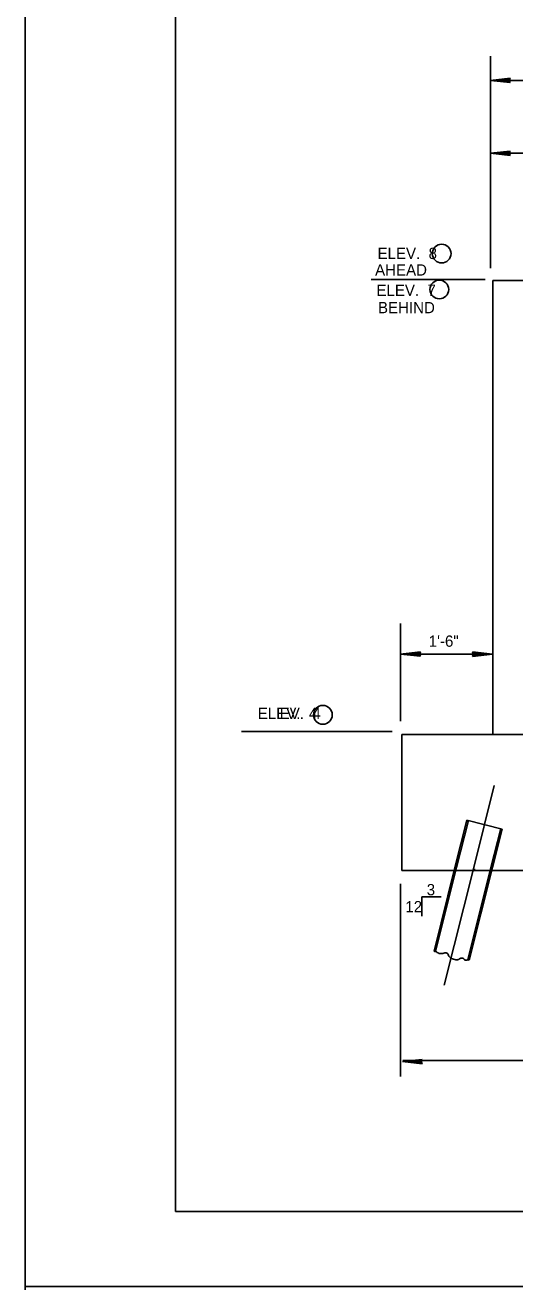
# Model space of a CAD drawing. Extents: x 1.6 to 6.29, y 2.8 to 7.08.
# Drawn here: x 2.391 to 2.935, y 4.671 to 6.075 of the extents above; entities that cross this region are included whole.
import ezdxf

# ---------------------------------------------------------------- set-up
doc = ezdxf.new("R2010")
doc.units = 0
doc.layers.add('Level 1', color=7, linetype='Continuous')
doc.layers.add('Level 5', color=7, linetype='Continuous')

msp = doc.modelspace()

# ---------------------------------------------------------------- linework, layer by layer
at = {"layer": 'Level 1'}
for p, q in [((2.3914, 7.0849), (2.3914, 4.6712)), ((2.5581, 6.998), (2.5581, 4.758)), ((2.9077, 5.8055), (2.9077, 6.041)), ((2.9077, 6.0142), (2.9297, 6.0167)), ((2.9077, 6.0142), (3.2259, 6.0142)), ((2.9297, 6.0142), (2.9077, 6.0142)), ((2.9297, 6.0118), (2.9077, 6.0142)), ((2.9133, 6.0146), (2.9107, 6.0143)), ((2.9107, 6.0143), (2.9282, 6.0144)), ((2.9113, 6.014), (2.9133, 6.0146)), ((2.9212, 6.0136), (2.9113, 6.014)), ((2.9292, 6.0121), (2.9128, 6.0139)), ((2.9292, 6.0122), (2.9128, 6.0139)), ((2.9292, 6.012), (2.9128, 6.0138)), ((2.9293, 6.0125), (2.9129, 6.0142)), ((2.9292, 6.0122), (2.9129, 6.0141)), ((2.9292, 6.0162), (2.9139, 6.0146)), ((2.9292, 6.0161), (2.9139, 6.0144)), ((2.9293, 6.0158), (2.914, 6.0142)), ((2.9293, 6.0156), (2.914, 6.0139)), ((2.9173, 6.0139), (2.9286, 6.0152)), ((2.9285, 6.0147), (2.9173, 6.0139)), ((2.9184, 6.0137), (2.9184, 6.014)), ((2.9184, 6.014), (2.9203, 6.0139)), ((2.9282, 6.0139), (2.9184, 6.0137)), ((2.9203, 6.0139), (2.9282, 6.0137)), ((2.9287, 6.013), (2.9212, 6.0136)), ((2.9282, 6.0137), (2.9219, 6.0136)), ((2.9219, 6.0136), (2.9285, 6.0134)), ((2.9282, 6.0144), (2.9231, 6.0147)), ((2.9231, 6.0147), (2.9285, 6.0147)), ((2.9285, 6.0134), (2.9238, 6.0133)), ((2.9238, 6.0133), (2.9287, 6.013)), ((2.9282, 6.0136), (2.9276, 6.0133)), ((2.9276, 6.0133), (2.928, 6.0127)), ((2.928, 6.0127), (2.9283, 6.0142)), ((2.9286, 6.0152), (2.9282, 6.0139)), ((2.9282, 6.0139), (2.9291, 6.0124)), ((2.9286, 6.0127), (2.9282, 6.0136)), ((2.9283, 6.0142), (2.9287, 6.0152)), ((2.9297, 6.0167), (2.9286, 6.0142)), ((2.9286, 6.0142), (2.9297, 6.0118)), ((2.9291, 6.0124), (2.9286, 6.0127)), ((2.9287, 6.0152), (2.9292, 6.0162)), ((2.9077, 5.9333), (3.5143, 5.9333)), ((2.9078, 5.9333), (2.9298, 5.9357)), ((2.9298, 5.9333), (2.9078, 5.9333)), ((2.9298, 5.9308), (2.9078, 5.9333)), ((2.9134, 5.9337), (2.9107, 5.9334)), ((2.9107, 5.9334), (2.9283, 5.9335)), ((2.9114, 5.9331), (2.9134, 5.9337)), ((2.9213, 5.9327), (2.9114, 5.9331)), ((2.9293, 5.9312), (2.9129, 5.933)), ((2.9293, 5.9312), (2.9129, 5.933)), ((2.9293, 5.9311), (2.9129, 5.9329)), ((2.9294, 5.9316), (2.913, 5.9333)), ((2.9293, 5.9313), (2.913, 5.9332)), ((2.9293, 5.9353), (2.914, 5.9337)), ((2.9293, 5.9352), (2.914, 5.9335)), ((2.9294, 5.9349), (2.9141, 5.9333)), ((2.9294, 5.9347), (2.9141, 5.933)), ((2.9173, 5.933), (2.9287, 5.9342)), ((2.9286, 5.9338), (2.9173, 5.933)), ((2.9185, 5.9328), (2.9185, 5.9331)), ((2.9185, 5.9331), (2.9204, 5.933)), ((2.9283, 5.933), (2.9185, 5.9328)), ((2.9204, 5.933), (2.9283, 5.9328)), ((2.9287, 5.9321), (2.9213, 5.9327)), ((2.9283, 5.9328), (2.922, 5.9327)), ((2.922, 5.9327), (2.9286, 5.9325)), ((2.9283, 5.9335), (2.9232, 5.9338)), ((2.9232, 5.9338), (2.9286, 5.9338)), ((2.9286, 5.9325), (2.9239, 5.9323)), ((2.9239, 5.9323), (2.9287, 5.9321)), ((2.9282, 5.9327), (2.9277, 5.9324)), ((2.9277, 5.9324), (2.9281, 5.9318)), ((2.9281, 5.9318), (2.9284, 5.9333)), ((2.9287, 5.9342), (2.9282, 5.933)), ((2.9282, 5.933), (2.9292, 5.9315)), ((2.9287, 5.9318), (2.9282, 5.9327)), ((2.9284, 5.9333), (2.9288, 5.9342)), ((2.9298, 5.9357), (2.9287, 5.9333)), ((2.9287, 5.9333), (2.9298, 5.9308)), ((2.9292, 5.9315), (2.9287, 5.9318)), ((2.9288, 5.9342), (2.9293, 5.9353)), ((2.7752, 5.793), (2.9018, 5.793)), ((2.9103, 5.2879), (2.9103, 5.7921)), ((2.9103, 5.7921), (3.2292, 5.7921)), ((2.9103, 5.2879), (2.9103, 5.4659)), ((2.8079, 5.3027), (2.8079, 5.4109)), ((2.8079, 5.3027), (2.8079, 5.3861)), ((2.8079, 5.377), (2.83, 5.3795)), ((2.8079, 5.377), (2.83, 5.3795)), ((2.8295, 5.3791), (2.8142, 5.3774)), ((2.8295, 5.3791), (2.8142, 5.3774)), ((2.8295, 5.3789), (2.8142, 5.3773)), ((2.8295, 5.3789), (2.8142, 5.3773)), ((2.8296, 5.3787), (2.8142, 5.377)), ((2.8296, 5.3787), (2.8142, 5.377)), ((2.8296, 5.3784), (2.8142, 5.3767)), ((2.8296, 5.3784), (2.8142, 5.3767)), ((2.83, 5.3795), (2.8288, 5.377)), ((2.83, 5.3795), (2.8288, 5.377)), ((2.829, 5.378), (2.8295, 5.3791)), ((2.829, 5.378), (2.8295, 5.3791)), ((2.8878, 5.3794), (2.9101, 5.377)), ((2.889, 5.377), (2.8878, 5.3794)), ((2.8878, 5.3794), (2.9101, 5.377)), ((2.889, 5.377), (2.8878, 5.3794)), ((2.8882, 5.3791), (2.9048, 5.3773)), ((2.8882, 5.3791), (2.9048, 5.3773)), ((2.8882, 5.379), (2.9048, 5.3772)), ((2.8882, 5.379), (2.9048, 5.3772)), ((2.8882, 5.3789), (2.9048, 5.3771)), ((2.8882, 5.3789), (2.9048, 5.3771)), ((2.8882, 5.3787), (2.9048, 5.3768)), ((2.8882, 5.3787), (2.9048, 5.3768)), ((2.8883, 5.3792), (2.9048, 5.3773)), ((2.8883, 5.3792), (2.9048, 5.3773)), ((2.8894, 5.3772), (2.8884, 5.3788)), ((2.8884, 5.3788), (2.8889, 5.3784)), ((2.8894, 5.3772), (2.8884, 5.3788)), ((2.8884, 5.3788), (2.8889, 5.3784)), ((2.8937, 5.3779), (2.8888, 5.3782)), ((2.8888, 5.3782), (2.8965, 5.3776)), ((2.8937, 5.3779), (2.8888, 5.3782)), ((2.8888, 5.3782), (2.8965, 5.3776)), ((2.8889, 5.3784), (2.8894, 5.3776)), ((2.8889, 5.3784), (2.8894, 5.3776)), ((2.8895, 5.3785), (2.8892, 5.3769)), ((2.8895, 5.3785), (2.8892, 5.3769)), ((2.8899, 5.3778), (2.8895, 5.3785)), ((2.8899, 5.3778), (2.8895, 5.3785)), ((2.83, 5.377), (2.8079, 5.377)), ((2.83, 5.3746), (2.8079, 5.377)), ((2.83, 5.377), (2.8079, 5.377)), ((2.83, 5.3746), (2.8079, 5.377)), ((2.8081, 5.377), (2.9072, 5.377)), ((2.8081, 5.377), (2.9072, 5.377)), ((2.8136, 5.3774), (2.8109, 5.3772)), ((2.8136, 5.3774), (2.8109, 5.3772)), ((2.8109, 5.3772), (2.8285, 5.3773)), ((2.8109, 5.3772), (2.8285, 5.3773)), ((2.8116, 5.3768), (2.8136, 5.3774)), ((2.8116, 5.3768), (2.8136, 5.3774)), ((2.8214, 5.3764), (2.8116, 5.3768)), ((2.8214, 5.3764), (2.8116, 5.3768)), ((2.8295, 5.3748), (2.8131, 5.3767)), ((2.8295, 5.3749), (2.8131, 5.3767)), ((2.8295, 5.375), (2.8131, 5.3767)), ((2.8295, 5.3748), (2.8131, 5.3767)), ((2.8295, 5.3749), (2.8131, 5.3767)), ((2.8295, 5.375), (2.8131, 5.3767)), ((2.8296, 5.3753), (2.8132, 5.3771)), ((2.8296, 5.3753), (2.8132, 5.3771)), ((2.8295, 5.3751), (2.8132, 5.3769)), ((2.8295, 5.3751), (2.8132, 5.3769)), ((2.8175, 5.3767), (2.8288, 5.378)), ((2.8175, 5.3767), (2.8288, 5.378)), ((2.8287, 5.3776), (2.8175, 5.3767)), ((2.8287, 5.3776), (2.8175, 5.3767)), ((2.8187, 5.3766), (2.8187, 5.3768)), ((2.8187, 5.3768), (2.8206, 5.3767)), ((2.8187, 5.3766), (2.8187, 5.3768)), ((2.8187, 5.3768), (2.8206, 5.3767)), ((2.8285, 5.3767), (2.8187, 5.3766)), ((2.8285, 5.3767), (2.8187, 5.3766)), ((2.8206, 5.3767), (2.8285, 5.3766)), ((2.8206, 5.3767), (2.8285, 5.3766)), ((2.8289, 5.3758), (2.8214, 5.3764)), ((2.8289, 5.3758), (2.8214, 5.3764)), ((2.8285, 5.3766), (2.8222, 5.3764)), ((2.8285, 5.3766), (2.8222, 5.3764)), ((2.8222, 5.3764), (2.8287, 5.3762)), ((2.8222, 5.3764), (2.8287, 5.3762)), ((2.8285, 5.3773), (2.8233, 5.3776)), ((2.8233, 5.3776), (2.8287, 5.3776)), ((2.8285, 5.3773), (2.8233, 5.3776)), ((2.8233, 5.3776), (2.8287, 5.3776)), ((2.8287, 5.3762), (2.8241, 5.3761)), ((2.8287, 5.3762), (2.8241, 5.3761)), ((2.8241, 5.3761), (2.8289, 5.3758)), ((2.8241, 5.3761), (2.8289, 5.3758)), ((2.8284, 5.3764), (2.8278, 5.3762)), ((2.8284, 5.3764), (2.8278, 5.3762)), ((2.8278, 5.3762), (2.8282, 5.3755)), ((2.8278, 5.3762), (2.8282, 5.3755)), ((2.8282, 5.3755), (2.8286, 5.3771)), ((2.8282, 5.3755), (2.8286, 5.3771)), ((2.8288, 5.378), (2.8284, 5.3767)), ((2.8288, 5.378), (2.8284, 5.3767)), ((2.8284, 5.3767), (2.8293, 5.3752)), ((2.8284, 5.3767), (2.8293, 5.3752)), ((2.8288, 5.3756), (2.8284, 5.3764)), ((2.8288, 5.3756), (2.8284, 5.3764)), ((2.8286, 5.3771), (2.829, 5.378)), ((2.8286, 5.3771), (2.829, 5.378)), ((2.8288, 5.377), (2.83, 5.3746)), ((2.8288, 5.377), (2.83, 5.3746)), ((2.8293, 5.3752), (2.8288, 5.3756)), ((2.8293, 5.3752), (2.8288, 5.3756)), ((2.8878, 5.377), (2.9101, 5.377)), ((2.9101, 5.377), (2.8878, 5.3745)), ((2.8878, 5.3745), (2.889, 5.377)), ((2.8878, 5.377), (2.9101, 5.377)), ((2.9101, 5.377), (2.8878, 5.3745)), ((2.8878, 5.3745), (2.889, 5.377)), ((2.8882, 5.3756), (2.9037, 5.3773)), ((2.8882, 5.3756), (2.9037, 5.3773)), ((2.8882, 5.3753), (2.9037, 5.377)), ((2.8882, 5.3753), (2.9037, 5.377)), ((2.8882, 5.3751), (2.9038, 5.3767)), ((2.8882, 5.3751), (2.9038, 5.3767)), ((2.8883, 5.3748), (2.9038, 5.3766)), ((2.8883, 5.3748), (2.9038, 5.3766)), ((2.8887, 5.376), (2.8883, 5.3749)), ((2.8887, 5.376), (2.8883, 5.3749)), ((2.8892, 5.3769), (2.8887, 5.376)), ((2.8892, 5.3769), (2.8887, 5.376)), ((2.9003, 5.3772), (2.8889, 5.376)), ((2.8889, 5.376), (2.8894, 5.3772)), ((2.9003, 5.3772), (2.8889, 5.376)), ((2.8889, 5.376), (2.8894, 5.3772)), ((2.8891, 5.3777), (2.8937, 5.3779)), ((2.8891, 5.3777), (2.8937, 5.3779)), ((2.8958, 5.3776), (2.8891, 5.3777)), ((2.8958, 5.3776), (2.8891, 5.3777)), ((2.8891, 5.3764), (2.9003, 5.3772)), ((2.8891, 5.3764), (2.9003, 5.3772)), ((2.8945, 5.3764), (2.8891, 5.3764)), ((2.8945, 5.3764), (2.8891, 5.3764)), ((2.8893, 5.3774), (2.8958, 5.3776)), ((2.8893, 5.3774), (2.8958, 5.3776)), ((2.8893, 5.3773), (2.8992, 5.3774)), ((2.8973, 5.3773), (2.8893, 5.3774)), ((2.8893, 5.3773), (2.8992, 5.3774)), ((2.8973, 5.3773), (2.8893, 5.3774)), ((2.9071, 5.3768), (2.8893, 5.3767)), ((2.9071, 5.3768), (2.8893, 5.3767)), ((2.8893, 5.3767), (2.8945, 5.3764)), ((2.8893, 5.3767), (2.8945, 5.3764)), ((2.8894, 5.3776), (2.8899, 5.3778)), ((2.8894, 5.3776), (2.8899, 5.3778)), ((2.8965, 5.3776), (2.9063, 5.3772)), ((2.8965, 5.3776), (2.9063, 5.3772)), ((2.8992, 5.3772), (2.8973, 5.3773)), ((2.8992, 5.3772), (2.8973, 5.3773)), ((2.8992, 5.3774), (2.8992, 5.3772)), ((2.8992, 5.3774), (2.8992, 5.3772)), ((2.9063, 5.3772), (2.9043, 5.3766)), ((2.9063, 5.3772), (2.9043, 5.3766)), ((2.9043, 5.3766), (2.9071, 5.3768)), ((2.9043, 5.3766), (2.9071, 5.3768)), ((2.6313, 5.2912), (2.7988, 5.2912)), ((2.6669, 5.2912), (2.7988, 5.2912)), ((2.8094, 5.1367), (2.8094, 5.2879)), ((2.8094, 5.2879), (2.9103, 5.2879)), ((2.8094, 5.1367), (2.8094, 5.2879)), ((2.8094, 5.2879), (2.9103, 5.2879)), ((2.9103, 5.2879), (3.2215, 5.2879)), ((2.9103, 5.2879), (3.2215, 5.2879)), ((3.2218, 5.1367), (2.8094, 5.1367)), ((3.2218, 5.1367), (2.8094, 5.1367)), ((2.8079, 5.122), (2.8079, 4.9079)), ((2.8079, 5.122), (2.8079, 4.9708)), ((2.81, 4.9245), (2.8321, 4.927)), ((2.81, 4.9245), (2.8321, 4.927)), ((2.8321, 4.9245), (2.81, 4.9245)), ((2.8321, 4.9221), (2.81, 4.9245)), ((2.8321, 4.9245), (2.81, 4.9245)), ((2.8321, 4.9221), (2.81, 4.9245)), ((2.8106, 4.9259), (3.2029, 4.9259)), ((2.8157, 4.9249), (2.813, 4.9247)), ((2.8157, 4.9249), (2.813, 4.9247)), ((2.813, 4.9247), (2.8306, 4.9247)), ((2.813, 4.9247), (2.8306, 4.9247)), ((2.8137, 4.9243), (2.8157, 4.9249)), ((2.8137, 4.9243), (2.8157, 4.9249)), ((2.8235, 4.9239), (2.8137, 4.9243)), ((2.8235, 4.9239), (2.8137, 4.9243)), ((2.8317, 4.9228), (2.8152, 4.9246)), ((2.8317, 4.9228), (2.8152, 4.9246)), ((2.8316, 4.9226), (2.8152, 4.9244)), ((2.8316, 4.9226), (2.8152, 4.9244)), ((2.8316, 4.9223), (2.8152, 4.9242)), ((2.8316, 4.9224), (2.8152, 4.9242)), ((2.8316, 4.9225), (2.8152, 4.9242)), ((2.8316, 4.9223), (2.8152, 4.9242)), ((2.8316, 4.9224), (2.8152, 4.9242)), ((2.8316, 4.9225), (2.8152, 4.9242)), ((2.8316, 4.9266), (2.8162, 4.9249)), ((2.8316, 4.9266), (2.8162, 4.9249)), ((2.8316, 4.9264), (2.8162, 4.9247)), ((2.8316, 4.9264), (2.8162, 4.9247)), ((2.8317, 4.9262), (2.8163, 4.9245)), ((2.8317, 4.9262), (2.8163, 4.9245)), ((2.8317, 4.9259), (2.8163, 4.9242)), ((2.8317, 4.9259), (2.8163, 4.9242)), ((2.8196, 4.9242), (2.8309, 4.9255)), ((2.8196, 4.9242), (2.8309, 4.9255)), ((2.8308, 4.9251), (2.8196, 4.9242)), ((2.8308, 4.9251), (2.8196, 4.9242)), ((2.8207, 4.9241), (2.8207, 4.9243)), ((2.8207, 4.9243), (2.8227, 4.9242)), ((2.8207, 4.9241), (2.8207, 4.9243)), ((2.8207, 4.9243), (2.8227, 4.9242)), ((2.8306, 4.9242), (2.8207, 4.9241)), ((2.8306, 4.9242), (2.8207, 4.9241)), ((2.8227, 4.9242), (2.8306, 4.9241)), ((2.8227, 4.9242), (2.8306, 4.9241)), ((2.831, 4.9233), (2.8235, 4.9239)), ((2.831, 4.9233), (2.8235, 4.9239)), ((2.8306, 4.9241), (2.8242, 4.9239)), ((2.8306, 4.9241), (2.8242, 4.9239)), ((2.8242, 4.9239), (2.8308, 4.9238)), ((2.8242, 4.9239), (2.8308, 4.9238)), ((2.8306, 4.9247), (2.8254, 4.9251)), ((2.8254, 4.9251), (2.8308, 4.9251)), ((2.8306, 4.9247), (2.8254, 4.9251)), ((2.8254, 4.9251), (2.8308, 4.9251)), ((2.8308, 4.9238), (2.8262, 4.9236)), ((2.8308, 4.9238), (2.8262, 4.9236)), ((2.8262, 4.9236), (2.831, 4.9233)), ((2.8262, 4.9236), (2.831, 4.9233)), ((2.8305, 4.9239), (2.8299, 4.9237)), ((2.8305, 4.9239), (2.8299, 4.9237)), ((2.8299, 4.9237), (2.8303, 4.923)), ((2.8299, 4.9237), (2.8303, 4.923)), ((2.8303, 4.923), (2.8307, 4.9246)), ((2.8303, 4.923), (2.8307, 4.9246)), ((2.8309, 4.9255), (2.8305, 4.9242)), ((2.8309, 4.9255), (2.8305, 4.9242)), ((2.8305, 4.9242), (2.8314, 4.9227)), ((2.8305, 4.9242), (2.8314, 4.9227)), ((2.8309, 4.9231), (2.8305, 4.9239)), ((2.8309, 4.9231), (2.8305, 4.9239)), ((2.8307, 4.9246), (2.8311, 4.9255)), ((2.8307, 4.9246), (2.8311, 4.9255)), ((2.8321, 4.927), (2.8309, 4.9245)), ((2.8321, 4.927), (2.8309, 4.9245)), ((2.8309, 4.9245), (2.8321, 4.9221)), ((2.8309, 4.9245), (2.8321, 4.9221)), ((2.8314, 4.9227), (2.8309, 4.9231)), ((2.8314, 4.9227), (2.8309, 4.9231)), ((2.8311, 4.9255), (2.8316, 4.9266)), ((2.8311, 4.9255), (2.8316, 4.9266)), ((2.5581, 4.758), (6.1848, 4.758)), ((2.5581, 4.758), (5.4647, 4.758)), ((2.3914, 4.6747), (6.2614, 4.6747))]:
    msp.add_line(p, q, dxfattribs=at)
for centre in [(2.8536, 5.8218), (2.851, 5.782), (2.7217, 5.3096), (2.7217, 5.3096)]:
    msp.add_circle(centre, 0.0104, dxfattribs=at)
at = {"layer": 'Level 5'}
for p, q in [((2.912, 5.2313), (2.8892, 5.14)), ((2.8815, 5.1926), (2.8683, 5.14)), ((2.8832, 5.1922), (2.8702, 5.14)), ((2.8815, 5.1926), (2.9207, 5.1828)), ((2.9191, 5.1833), (2.9082, 5.14)), ((2.9207, 5.1828), (2.91, 5.14)), ((2.8683, 5.14), (2.8452, 5.0471)), ((2.8702, 5.14), (2.8468, 5.0467)), ((2.8892, 5.14), (2.8565, 5.0092)), ((2.9082, 5.14), (2.8827, 5.0377)), ((2.91, 5.14), (2.8843, 5.0373)), ((2.853, 5.1074), (2.8317, 5.1074)), ((2.8317, 5.1074), (2.8317, 5.0861))]:
    msp.add_line(p, q, dxfattribs=at)
msp.add_spline([(2.8452, 5.0471), (2.8468, 5.0467), (2.8506, 5.0447), (2.8548, 5.0447), (2.8571, 5.0452), (2.8599, 5.0447), (2.8603, 5.0442), (2.8613, 5.0424), (2.8622, 5.041), (2.8655, 5.0387), (2.8682, 5.0377), (2.872, 5.0377), (2.8747, 5.0392), (2.8785, 5.0382), (2.8794, 5.0373), (2.8817, 5.0373), (2.8827, 5.0377), (2.8843, 5.0373)], degree=3, dxfattribs=at)

# ---------------------------------------------------------------- texts
at = {"layer": 'Level 1'}
msp.add_text('1\'-6"', height=0.0125, dxfattribs=at).set_placement((2.8392, 5.3852))
msp.add_text('1\'-6"', height=0.0125, dxfattribs=at).set_placement((2.8392, 5.3852))
at = {"layer": 'Level 5'}
for s, p in [('ELEV.  8', (2.7824, 5.8158)), ('AHEAD', (2.7797, 5.7974)), ('ELEV.  7', (2.7812, 5.7749)), ('BEHIND', (2.7829, 5.7556)), ('ELEV.  4', (2.6495, 5.3049)), ('EV.  4', (2.6738, 5.3049)), ('.', (2.8878, 5.1367)), ('3', (2.837, 5.1092)), ('12', (2.8133, 5.0903))]:
    msp.add_text(s, height=0.0125, dxfattribs=at).set_placement(p)

doc.saveas('drawing.dxf')
